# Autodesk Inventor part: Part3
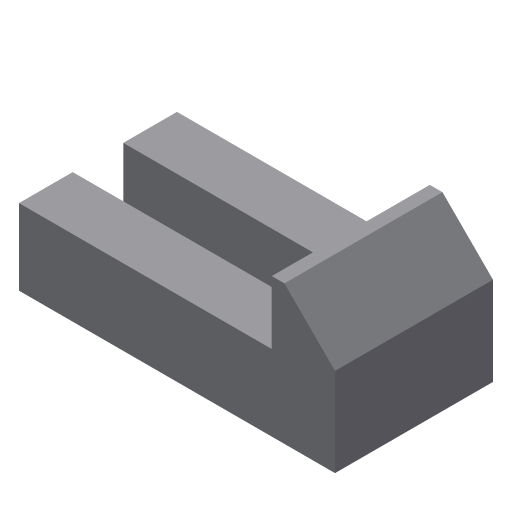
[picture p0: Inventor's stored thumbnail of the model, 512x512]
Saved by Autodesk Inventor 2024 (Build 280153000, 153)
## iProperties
Shininess: 77.0
Length Units: 11269
Angle Units: 11279
Time Units: 11290
Mass Units: 11283
Length Display Precision: 3
Angle Display Precision: 2
Created: 2002-01
Part Number: Part3
Document SubType Name: Modeling
Designer: ***
Density: 1 g/cm^3
Material: Generic
Appearance: Default
Density: 0.0
Volumn: 0.0
Area: 0.0
PropertySet Name: Model Information
Control State: 0
Master: False
Checked Out: False
Author: ***
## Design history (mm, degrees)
sketch "Sketch2"
  geometry: L1 (23.289, -5.477)-(-16.711, -5.477); L2 (-16.711, -5.477)-(-16.711, 4.523); L3 (-16.711, 4.523)-(-18.711, 4.523); L4 (-18.711, 4.523)-(-26.711, -3.477); L5 (-26.711, -3.477)-(-26.711, -17.477); L6 (-26.711, -17.477)-(23.289, -17.477); L7 (23.289, -17.477)-(23.289, -5.477)
  constraints: 14 end point, 4 parallel, 1 horizontal, 1 perpendicular
  dimensions: "d0" = 50 distance of L5.end L6.end; "d1" = 12 distance of L6.end L1.start; "d2" = 22 distance between parallel lines of L3 L6; "d3" = 135 deg angle of L5 L4; "d4" = 2 distance of L2.end L3.end; "d5" = 40 distance of L1.start L1.end
extrude "Extrusion1" new body sketch "Sketch2" stored distance "d6" = 25; taper "d7" = 0 deg
sketch "Sketch3"
  geometry: L1 (-4, -8.5)-(36, -8.5); L2 (36, -8.5)-(36, -16.5); L3 (36, -16.5)-(-4, -16.5); L4 (-4, -16.5)-(-4, -8.5); L5 (40, -25)-(40, 0) reference; L6 (40, 0)-(0, 0) reference
  constraints: 8 end point, 2 parallel, 1 horizontal, 1 perpendicular
  dimensions: "d8" = 8 distance of L1.end L2.end; "d9" = 40 distance of L1.start L1.end; "d10" = 4 distance between parallel lines of L5 L2; "d11" = 8.5 distance between parallel lines of L6 L1
extrude "Extrusion2" cut sketch "Sketch3" extent not by distance; stored distance "d12" = 25; taper "d13" = 0 deg
body "Solid1"
